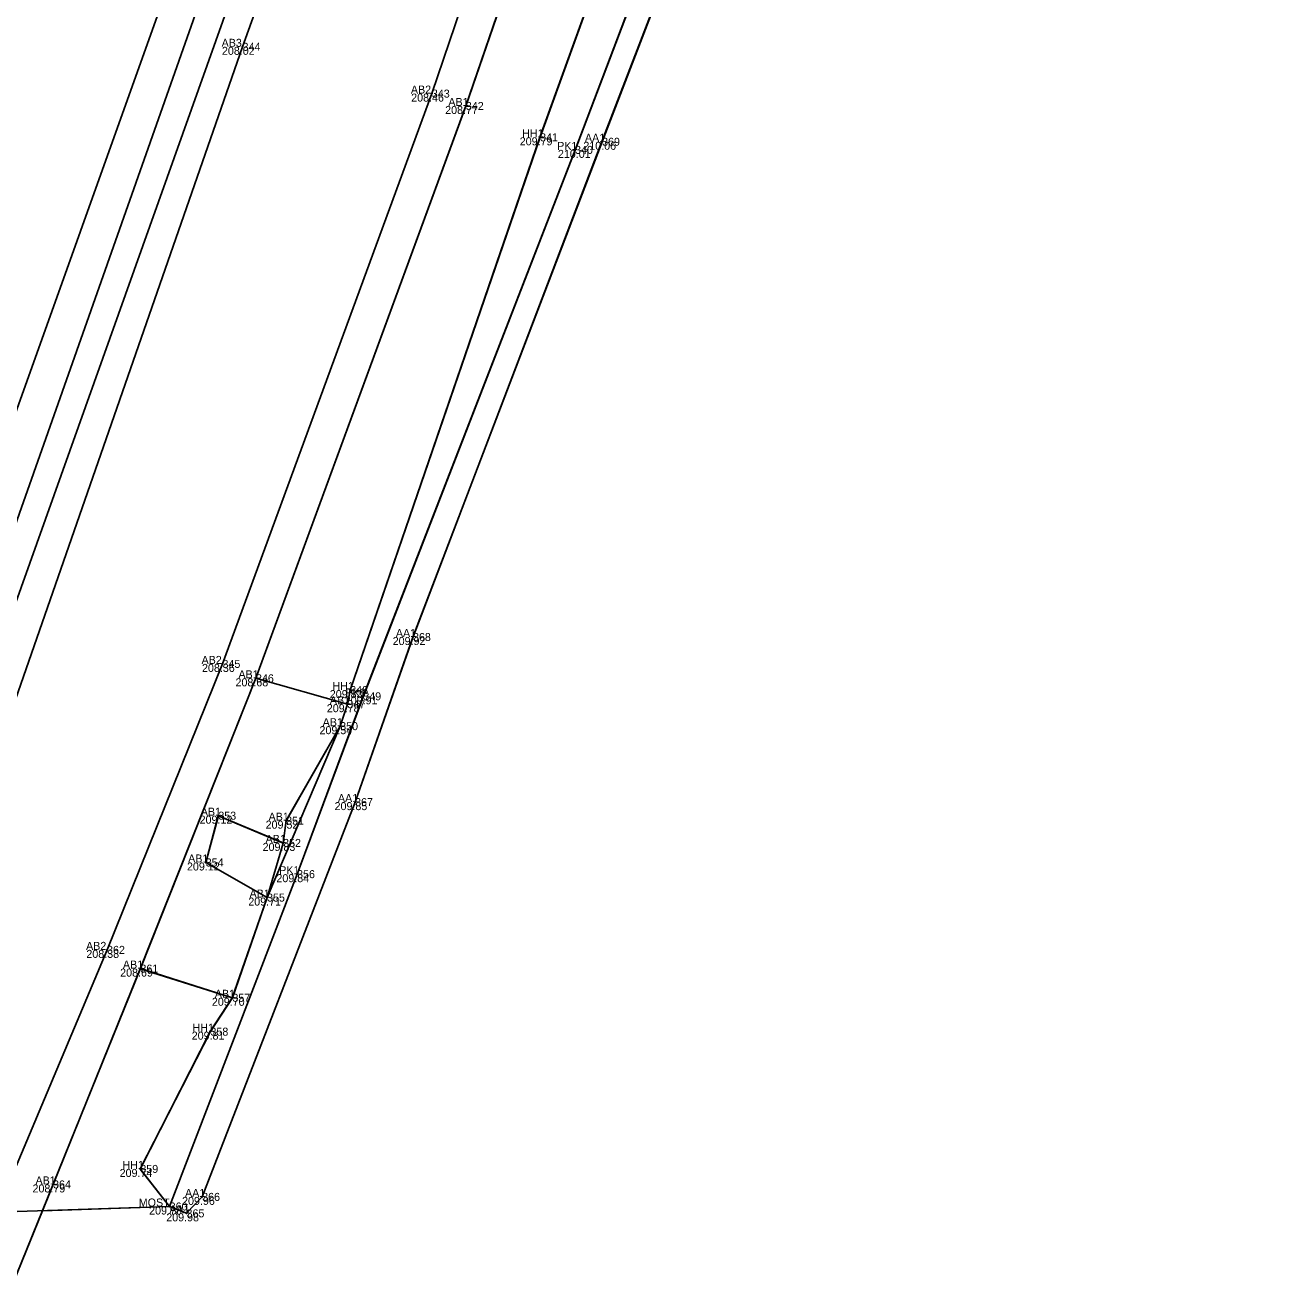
# Model space of a CAD drawing. Extents: x -263091 to -262565, y -1238731 to -1237092.
# Drawn here: x -262895.63 to -262864.26, y -1238240.38 to -1238208.92 of the extents above; entities that cross this region are included whole.
import ezdxf

# ---------------------------------------------------------------- set-up
doc = ezdxf.new("R2010")
doc.units = 0
for name, color, linetype in [('01_Hrana_betónu', 7, 'Continuous'), ('02_Oplotenie', 7, 'Continuous'), ('03_Asfalt', 7, 'Continuous'), ('04_Most', 7, 'Continuous'), ('05_Hrana_terénu', 7, 'Continuous'), ('07_Iné', 7, 'Continuous'), ('Groma (21)', 7, 'Continuous'), ('Groma (22)', 7, 'Continuous'), ('Groma (23)', 7, 'Continuous'), ('Groma (24)', 7, 'Continuous'), ('U002_Zeleň_zatrávňovač', 7, 'Continuous'), ('U003_Betónové_panely', 7, 'Continuous'), ('U003_Betóny_prídavné', 7, 'Continuous'), ('U003_Zeleň_mimo', 7, 'Continuous'), ('U003_Zeleň_vnútro', 7, 'Continuous'), ('U003_Zeleň_zatrávňovač', 7, 'Continuous'), ('U005_Betóny_prídavné', 7, 'Continuous')]:
    doc.layers.add(name, color=color, linetype=linetype)

msp = doc.modelspace()

# ---------------------------------------------------------------- linework, layer by layer
at = {"layer": '01_Hrana_betónu'}
msp.add_line((-262900.833, -1238252.4), (-262895.195, -1238238.545), dxfattribs=at)
for points in [[(-262903.088, -1238238.797), (-262890.817, -1238204.479), (-262885.468, -1238189.492), (-262878.003, -1238168.56), (-262870.455, -1238147.513), (-262864.947, -1238132.168), (-262859.037, -1238116.651), (-262848.977, -1238095.826), (-262842.353, -1238078.361), (-262839.446, -1238067.823), (-262836.783, -1238055.069), (-262834.905, -1238040.999), (-262833.763, -1238025.462), (-262832.297, -1238000.555), (-262831.13, -1237981.111), (-262829.791, -1237958.391), (-262828.651, -1237937.03), (-262828.571, -1237935.876)], [(-262827.762, -1237935.927), (-262827.853, -1237937.062), (-262829.049, -1237958.415), (-262830.305, -1237981.211), (-262831.433, -1238000.629), (-262832.987, -1238025.43), (-262834.086, -1238041.027), (-262836.169, -1238055.023), (-262838.684, -1238068.024), (-262841.681, -1238078.569), (-262848.285, -1238096.308), (-262858.162, -1238116.913), (-262863.876, -1238132.122), (-262869.919, -1238147.692), (-262877.244, -1238168.638), (-262884.69, -1238189.67), (-262901.991, -1238238.762)], [(-262827.034, -1237935.973), (-262827.072, -1237937.036), (-262828.491, -1237960.168), (-262829.643, -1237980.454), (-262830.754, -1238002.123), (-262832.4, -1238026.024), (-262833.369, -1238041.644), (-262835.263, -1238055.011), (-262838.048, -1238068.261), (-262841.826, -1238081.232), (-262846.645, -1238094.136), (-262857.777, -1238117.273), (-262863.292, -1238131.948), (-262884.082, -1238190.299), (-262901.352, -1238238.742)], [(-262900.376, -1238238.711), (-262890.192, -1238209.46), (-262883.463, -1238190.564), (-262868.512, -1238148.877), (-262862.514, -1238132.276), (-262857.014, -1238117.706), (-262845.846, -1238094.561), (-262841.058, -1238081.49), (-262837.218, -1238068.474), (-262834.492, -1238055.416), (-262832.606, -1238041.772), (-262831.509, -1238026.143), (-262830.024, -1238002.24), (-262828.826, -1237980.518), (-262827.576, -1237960.277), (-262826.117, -1237937.218), (-262826.079, -1237936.033)], [(-262896.34, -1238238.582), (-262893.58, -1238232.03), (-262890.694, -1238224.883), (-262885.46, -1238210.629), (-262879.076, -1238191.844), (-262872.3, -1238172.74), (-262864.174, -1238150.334), (-262858.102, -1238133.93), (-262852.288, -1238119.39), (-262842.616, -1238095.519), (-262840.924, -1238094.827)], [(-262895.195, -1238238.545), (-262892.745, -1238232.498), (-262889.857, -1238225.243), (-262884.61, -1238210.939), (-262878.158, -1238192.142), (-262871.406, -1238173.111), (-262863.323, -1238150.734), (-262857.2, -1238134.123), (-262851.463, -1238119.84), (-262841.762, -1238095.81), (-262840.6, -1238094.732)]]:
    msp.add_lwpolyline(points, dxfattribs=at)
at = {"layer": '02_Oplotenie'}
msp.add_lwpolyline([(-262819.762, -1237938.034), (-262820.788, -1237960.675), (-262821.837, -1237980.919), (-262823.308, -1238002.106), (-262824.582, -1238026.068), (-262825.82, -1238041.973), (-262827.772, -1238056.552), (-262830.57, -1238069.546), (-262834.589, -1238083.855), (-262839.328, -1238095.835), (-262848.782, -1238120.942), (-262853.684, -1238135.175), (-262859.896, -1238152.781), (-262867.698, -1238174.329), (-262874.833, -1238193.487), (-262881.88, -1238212.036), (-262887.174, -1238225.693), (-262888.829, -1238230.138)], dxfattribs=at)
at = {"layer": '03_Asfalt'}
msp.add_lwpolyline([(-262836.859, -1238089.782), (-262836.111, -1238090.171), (-262839.692, -1238097.821), (-262843.275, -1238106.507), (-262847.806, -1238119.202), (-262853.613, -1238135.97), (-262859.461, -1238152.467), (-262860.389, -1238156.54), (-262862.798, -1238164.04), (-262866.716, -1238174.359), (-262874.069, -1238193.289), (-262881.205, -1238211.833), (-262885.932, -1238224.211), (-262887.38, -1238228.337), (-262891.202, -1238238.204), (-262891.593, -1238238.614)], dxfattribs=at)
at = {"layer": '04_Most'}
msp.add_line((-262892.015, -1238238.444), (-262912.678, -1238239.103), dxfattribs=at)
at = {"layer": '05_Hrana_terénu'}
msp.add_lwpolyline([(-262892.015, -1238238.444), (-262892.748, -1238237.505), (-262890.995, -1238234.074), (-262890.447, -1238233.227), (-262889.58, -1238230.723), (-262887.752, -1238226.439), (-262887.573, -1238225.89), (-262887.5, -1238225.537), (-262882.755, -1238211.722), (-262875.967, -1238192.943), (-262869.149, -1238173.959), (-262860.962, -1238151.685), (-262855.003, -1238134.792), (-262849.564, -1238120.544), (-262839.894, -1238095.583)], dxfattribs=at)
at = {"layer": '07_Iné'}
msp.add_lwpolyline([(-262889.857, -1238225.243), (-262887.573, -1238225.89), (-262887.752, -1238226.439), (-262889.104, -1238228.801), (-262889.179, -1238229.357), (-262890.798, -1238228.676), (-262891.114, -1238229.846), (-262889.58, -1238230.723), (-262890.447, -1238233.227), (-262892.745, -1238232.498)], dxfattribs=at)
at = {"layer": 'Groma (21)'}
for centre in [(-262890.192, -1238209.46), (-262885.46, -1238210.629), (-262884.61, -1238210.939), (-262882.755, -1238211.722), (-262881.88, -1238212.036), (-262881.205, -1238211.833), (-262885.932, -1238224.211), (-262890.694, -1238224.883), (-262889.857, -1238225.243), (-262887.5, -1238225.537), (-262887.174, -1238225.693), (-262887.573, -1238225.89), (-262887.752, -1238226.439), (-262887.38, -1238228.337), (-262890.798, -1238228.676), (-262889.104, -1238228.801), (-262889.179, -1238229.357), (-262891.114, -1238229.846), (-262888.829, -1238230.138), (-262889.58, -1238230.723), (-262893.58, -1238232.03), (-262892.745, -1238232.498), (-262890.447, -1238233.227), (-262890.995, -1238234.074), (-262892.748, -1238237.505), (-262894.93, -1238237.892), (-262892.015, -1238238.444), (-262891.202, -1238238.204), (-262891.593, -1238238.614)]:
    msp.add_circle(centre, 0.01, dxfattribs=at)
at = {"layer": 'U002_Zeleň_zatrávňovač'}
msp.add_lwpolyline([(-262895.19, -1238238.55), (-262892.75, -1238232.5), (-262890.45, -1238233.23), (-262891, -1238234.07), (-262892.75, -1238237.51), (-262892.02, -1238238.44), (-262895.19, -1238238.55)], dxfattribs=at)
at = {"layer": 'U003_Betónové_panely'}
msp.add_lwpolyline([(-262822, -1237934.47), (-262822.23, -1237936.28), (-262821.72, -1237936.34), (-262823.03, -1237960.34), (-262824.32, -1237980.84), (-262825.49, -1238001.86), (-262826.83, -1238026.47), (-262828.06, -1238041.94), (-262830.21, -1238056.42), (-262832.97, -1238069.04), (-262836.94, -1238083.07), (-262840.92, -1238094.83), (-262840.6, -1238094.73), (-262841.76, -1238095.81), (-262851.46, -1238119.84), (-262857.2, -1238134.12), (-262863.32, -1238150.73), (-262871.41, -1238173.11), (-262878.16, -1238192.14), (-262884.61, -1238210.94), (-262889.86, -1238225.24), (-262892.75, -1238232.5), (-262895.19, -1238238.55), (-262900.83, -1238252.4)], dxfattribs=at)
msp.add_lwpolyline([(-262822, -1237934.47), (-262822.23, -1237936.28), (-262821.72, -1237936.34), (-262823.03, -1237960.34), (-262824.32, -1237980.84), (-262825.49, -1238001.86), (-262826.83, -1238026.47), (-262828.06, -1238041.94), (-262830.21, -1238056.42), (-262832.97, -1238069.04), (-262836.94, -1238083.07), (-262840.92, -1238094.83), (-262840.6, -1238094.73), (-262841.76, -1238095.81), (-262851.46, -1238119.84), (-262857.2, -1238134.12), (-262863.32, -1238150.73), (-262871.41, -1238173.11), (-262878.16, -1238192.14), (-262884.61, -1238210.94), (-262889.86, -1238225.24), (-262892.75, -1238232.5), (-262895.19, -1238238.55), (-262900.83, -1238252.4)], dxfattribs=at)
at = {"layer": 'U003_Betóny_prídavné'}
msp.add_lwpolyline([(-262892.75, -1238232.5), (-262889.86, -1238225.24), (-262887.57, -1238225.89), (-262887.75, -1238226.44), (-262889.1, -1238228.8), (-262889.18, -1238229.36), (-262890.8, -1238228.68), (-262891.11, -1238229.85), (-262889.58, -1238230.72), (-262890.45, -1238233.23)], close=True, dxfattribs=at)
msp.add_lwpolyline([(-262890.45, -1238233.23), (-262892.75, -1238232.5), (-262889.86, -1238225.24), (-262887.57, -1238225.89), (-262887.75, -1238226.44), (-262889.1, -1238228.8), (-262889.18, -1238229.36), (-262890.8, -1238228.68), (-262891.11, -1238229.85), (-262889.58, -1238230.72), (-262890.45, -1238233.23)], dxfattribs=at)
at = {"layer": 'U003_Zeleň_mimo'}
msp.add_lwpolyline([(-262843.28, -1238106.51), (-262847.81, -1238119.2), (-262853.61, -1238135.97), (-262859.46, -1238152.47), (-262860.39, -1238156.54), (-262862.8, -1238164.04), (-262866.72, -1238174.36), (-262874.07, -1238193.29), (-262881.21, -1238211.83), (-262885.93, -1238224.21), (-262887.38, -1238228.34), (-262891.2, -1238238.2), (-262891.59, -1238238.61), (-262892.02, -1238238.44), (-262888.83, -1238230.14), (-262887.17, -1238225.69), (-262881.88, -1238212.04), (-262874.83, -1238193.49), (-262867.7, -1238174.33), (-262859.9, -1238152.78), (-262853.68, -1238135.18), (-262848.78, -1238120.94), (-262839.33, -1238095.84)], dxfattribs=at)
at = {"layer": 'U003_Zeleň_vnútro'}
for points in [[(-262892.02, -1238238.44), (-262892.75, -1238237.51), (-262891, -1238234.07), (-262890.45, -1238233.23), (-262889.58, -1238230.72), (-262889.18, -1238229.36), (-262889.1, -1238228.8), (-262887.75, -1238226.44), (-262887.57, -1238225.89), (-262887.5, -1238225.54), (-262882.76, -1238211.72), (-262875.97, -1238192.94), (-262869.15, -1238173.96), (-262860.96, -1238151.69), (-262855, -1238134.79), (-262849.56, -1238120.54), (-262839.89, -1238095.58)], [(-262839.33, -1238095.84), (-262848.78, -1238120.94), (-262853.68, -1238135.18), (-262859.9, -1238152.78), (-262867.7, -1238174.33), (-262874.83, -1238193.49), (-262881.88, -1238212.04), (-262887.17, -1238225.69), (-262888.83, -1238230.14), (-262892.02, -1238238.44)], [(-262867.7, -1238174.33), (-262874.83, -1238193.49), (-262881.88, -1238212.04), (-262887.17, -1238225.69), (-262888.83, -1238230.14), (-262892.02, -1238238.44), (-262892.75, -1238237.51), (-262891, -1238234.07), (-262890.45, -1238233.23), (-262889.58, -1238230.72), (-262889.18, -1238229.36), (-262889.1, -1238228.8), (-262887.75, -1238226.44), (-262887.57, -1238225.89), (-262887.5, -1238225.54), (-262882.76, -1238211.72), (-262875.97, -1238192.94), (-262869.15, -1238173.96)]]:
    msp.add_lwpolyline(points, dxfattribs=at)
at = {"layer": 'U003_Zeleň_zatrávňovač'}
msp.add_lwpolyline([(-262839.89, -1238095.58), (-262849.56, -1238120.54), (-262855, -1238134.79), (-262860.96, -1238151.69), (-262869.15, -1238173.96), (-262875.97, -1238192.94), (-262882.76, -1238211.72), (-262887.5, -1238225.54), (-262887.57, -1238225.89), (-262889.86, -1238225.24), (-262884.61, -1238210.94), (-262878.16, -1238192.14), (-262871.41, -1238173.11), (-262863.32, -1238150.73), (-262857.2, -1238134.12), (-262851.46, -1238119.84), (-262841.76, -1238095.81)], dxfattribs=at)
for points in [[(-262889.58, -1238230.72), (-262891.11, -1238229.85), (-262890.8, -1238228.68), (-262889.18, -1238229.36)], [(-262891, -1238234.07), (-262892.75, -1238237.51), (-262892.02, -1238238.44), (-262895.19, -1238238.55), (-262892.75, -1238232.5), (-262890.45, -1238233.23)]]:
    msp.add_lwpolyline(points, close=True, dxfattribs=at)
at = {"layer": 'U005_Betóny_prídavné'}
for points in [[(-262839.89, -1238095.58), (-262849.56, -1238120.54), (-262855, -1238134.79), (-262860.96, -1238151.69), (-262869.15, -1238173.96), (-262875.97, -1238192.94), (-262882.76, -1238211.72), (-262887.5, -1238225.54), (-262887.57, -1238225.89)], [(-262887.57, -1238225.89), (-262889.86, -1238225.24), (-262884.61, -1238210.94), (-262878.16, -1238192.14), (-262871.41, -1238173.11), (-262863.32, -1238150.73), (-262857.2, -1238134.12), (-262851.46, -1238119.84), (-262841.76, -1238095.81)]]:
    msp.add_lwpolyline(points, dxfattribs=at)

# ---------------------------------------------------------------- texts
at = {"layer": 'Groma (22)'}
for s, p in [('344', (-262890.192, -1238209.56)), ('343', (-262885.46, -1238210.729)), ('342', (-262884.61, -1238211.039)), ('341', (-262882.755, -1238211.822)), ('340', (-262881.88, -1238212.136)), ('369', (-262881.205, -1238211.933)), ('368', (-262885.932, -1238224.311)), ('345', (-262890.694, -1238224.983)), ('346', (-262889.857, -1238225.343)), ('348', (-262887.5, -1238225.637)), ('347', (-262887.573, -1238225.99)), ('349', (-262887.174, -1238225.793)), ('350', (-262887.752, -1238226.539)), ('367', (-262887.38, -1238228.437)), ('353', (-262890.798, -1238228.776)), ('351', (-262889.104, -1238228.901)), ('352', (-262889.179, -1238229.457)), ('354', (-262891.114, -1238229.946)), ('356', (-262888.829, -1238230.238)), ('355', (-262889.58, -1238230.823)), ('362', (-262893.58, -1238232.13)), ('361', (-262892.745, -1238232.598)), ('357', (-262890.447, -1238233.327)), ('358', (-262890.995, -1238234.174)), ('359', (-262892.748, -1238237.605)), ('364', (-262894.93, -1238237.992)), ('366', (-262891.202, -1238238.304)), ('360', (-262892.015, -1238238.544)), ('365', (-262891.593, -1238238.714))]:
    msp.add_text(s, height=0.2, dxfattribs=at).set_placement(p)
at = {"layer": 'Groma (23)'}
for s, p in [('208.02', (-262890.708, -1238209.66)), ('208.46', (-262885.977, -1238210.829)), ('208.77', (-262885.128, -1238211.139)), ('209.79', (-262883.263, -1238211.922)), ('210.01', (-262882.309, -1238212.236)), ('210.06', (-262881.673, -1238212.033)), ('209.92', (-262886.439, -1238224.411)), ('208.36', (-262891.206, -1238225.083)), ('208.68', (-262890.369, -1238225.443)), ('209.83', (-262888.012, -1238225.737)), ('209.91', (-262887.638, -1238225.893)), ('209.78', (-262888.086, -1238226.09)), ('209.54', (-262888.269, -1238226.639)), ('209.85', (-262887.892, -1238228.537)), ('209.12', (-262891.266, -1238228.876)), ('209.52', (-262889.616, -1238229.001)), ('209.83', (-262889.691, -1238229.557)), ('209.12', (-262891.582, -1238230.046)), ('209.84', (-262889.346, -1238230.338)), ('209.71', (-262890.049, -1238230.923)), ('208.38', (-262894.097, -1238232.23)), ('208.69', (-262893.252, -1238232.698)), ('209.70', (-262890.959, -1238233.427)), ('209.81', (-262891.463, -1238234.274)), ('209.74', (-262893.265, -1238237.705)), ('208.79', (-262895.443, -1238238.092)), ('209.78', (-262892.528, -1238238.644)), ('209.96', (-262891.704, -1238238.404)), ('209.98', (-262892.1, -1238238.814))]:
    msp.add_text(s, height=0.2, dxfattribs=at).set_placement(p)
at = {"layer": 'Groma (24)'}
for s, p in [('AB3', (-262890.716, -1238209.46)), ('AB2', (-262885.984, -1238210.629)), ('AB1', (-262885.048, -1238210.939)), ('HH1', (-262883.202, -1238211.722)), ('AA1', (-262881.633, -1238211.833)), ('PK1', (-262882.327, -1238212.036)), ('AA1', (-262886.36, -1238224.211)), ('AB2', (-262891.218, -1238224.883)), ('AB1', (-262890.295, -1238225.243)), ('HH1', (-262887.947, -1238225.537)), ('PK1', (-262887.621, -1238225.693)), ('AB1', (-262888.011, -1238225.89)), ('AB1', (-262888.19, -1238226.439)), ('AA1', (-262887.808, -1238228.337)), ('AB1', (-262891.236, -1238228.676)), ('AB1', (-262889.542, -1238228.801)), ('AB1', (-262889.617, -1238229.357)), ('AB1', (-262891.552, -1238229.846)), ('PK1', (-262889.276, -1238230.138)), ('AB1', (-262890.018, -1238230.723)), ('AB2', (-262894.104, -1238232.03)), ('AB1', (-262893.183, -1238232.498)), ('AB1', (-262890.885, -1238233.227)), ('HH1', (-262891.442, -1238234.074)), ('HH1', (-262893.195, -1238237.505)), ('AB1', (-262895.368, -1238237.892)), ('AA1', (-262891.63, -1238238.204)), ('MOST', (-262892.787, -1238238.444)), ('AA1', (-262892.021, -1238238.614))]:
    msp.add_text(s, height=0.2, dxfattribs=at).set_placement(p)

doc.saveas('drawing.dxf')
